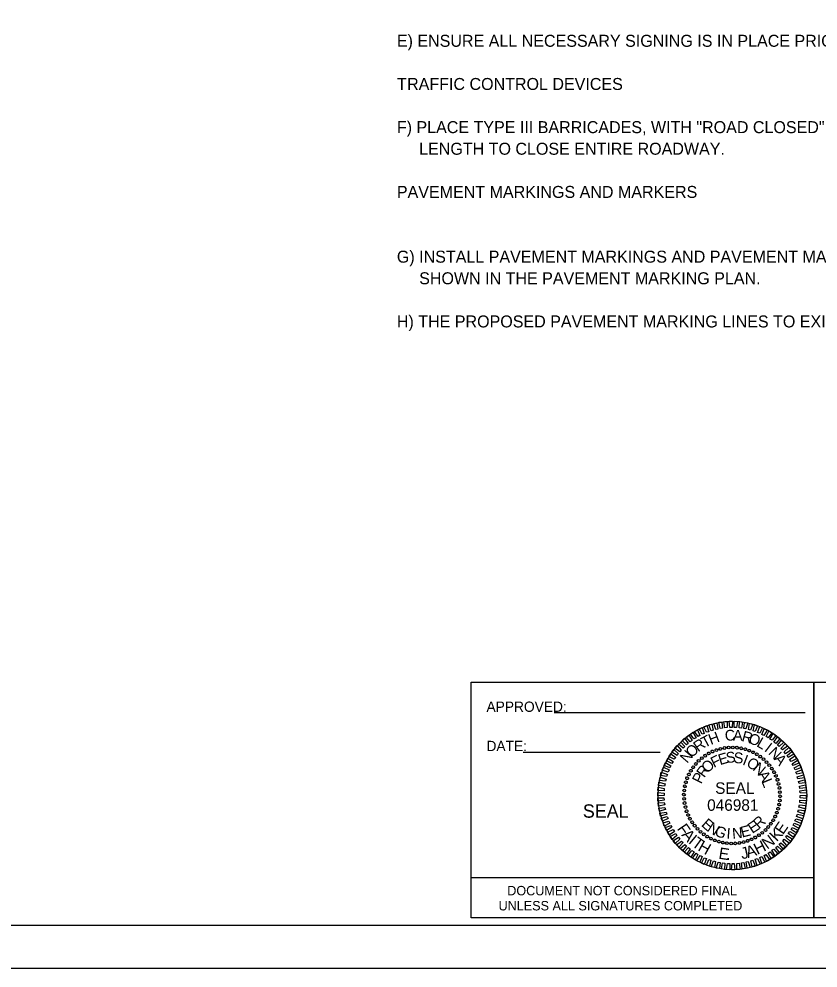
# Model space of a CAD drawing. Extents: x -38542 to 45858, y -25814 to 29186.
# Drawn here: x 1012 to 1478, y -628 to -74 of the extents above; entities that cross this region are included whole.
import ezdxf

# ---------------------------------------------------------------- set-up
doc = ezdxf.new("R2010")
doc.units = 0
for name, color, linetype in [('DEV PORTABLE SIGN CELL', 7, 'Continuous'), ('Exist Road Non-System Type 51 Label', 7, 'Continuous'), ('Sheet Plan CELL', 7, 'Continuous'), ('Sheet Plot Border Outside CELL', 7, 'Continuous'), ('WZ DETAHD CELL', 7, 'Continuous'), ('WZ RC1000 CELL', 7, 'Continuous'), ('WZ RCANR CELL', 7, 'Continuous')]:
    doc.layers.add(name, color=color, linetype=linetype)

msp = doc.modelspace()

# ---------------------------------------------------------------- linework, layer by layer
at = {"layer": 'DEV PORTABLE SIGN CELL'}
for p, q in [((1414.41, -503.12), (1414.41, -503.12)), ((1416.59, -502), (1416.59, -502)), ((1418.83, -501.11), (1418.83, -501.11)), ((1421.17, -500.43), (1421.17, -500.43)), ((1423.63, -499.99), (1423.63, -499.99)), ((1426.03, -499.65), (1426.03, -499.65)), ((1428.49, -499.6), (1428.49, -499.6)), ((1430.95, -499.76), (1430.95, -499.76)), ((1433.35, -500.16), (1433.35, -500.16)), ((1435.7, -500.66), (1435.7, -500.66)), ((1438.05, -501.44), (1438.05, -501.44)), ((1440.28, -502.45), (1440.28, -502.45)), ((1442.46, -503.56), (1442.46, -503.56)), ((1406.81, -509.21), (1406.81, -509.21)), ((1408.49, -507.48), (1408.49, -507.48)), ((1410.33, -505.8), (1410.33, -505.8)), ((1412.29, -504.4), (1412.29, -504.4)), ((1444.48, -504.96), (1444.48, -504.96)), ((1446.43, -506.47), (1446.43, -506.47)), ((1448.16, -508.15), (1448.16, -508.15)), ((1403.9, -513.18), (1403.9, -513.18)), ((1405.3, -511.16), (1405.3, -511.16)), ((1449.84, -509.99), (1449.84, -509.99)), ((1451.24, -511.95), (1451.24, -511.95)), ((1452.52, -514.07), (1452.52, -514.07)), ((1401, -519.94), (1401, -519.94)), ((1401.78, -517.59), (1401.78, -517.59)), ((1402.79, -515.36), (1402.79, -515.36)), ((1453.64, -516.25), (1453.64, -516.25)), ((1454.53, -518.48), (1454.53, -518.48)), ((1400.1, -524.69), (1400.1, -524.69)), ((1400.5, -522.28), (1400.5, -522.28)), ((1455.21, -520.83), (1455.21, -520.83)), ((1455.65, -523.29), (1455.65, -523.29)), ((1455.99, -525.69), (1455.99, -525.69)), ((1399.94, -527.15), (1399.94, -527.15)), ((1399.99, -529.61), (1399.99, -529.61)), ((1427.99, -527.65), (1427.99, -527.65)), ((1455.88, -530.61), (1455.88, -530.61)), ((1456.04, -528.15), (1456.04, -528.15)), ((1400.33, -532.01), (1400.33, -532.01)), ((1400.77, -534.47), (1400.77, -534.47)), ((1401.45, -536.81), (1401.45, -536.81)), ((1454.98, -535.36), (1454.98, -535.36)), ((1455.48, -533.01), (1455.48, -533.01)), ((1402.34, -539.05), (1402.34, -539.05)), ((1403.46, -541.23), (1403.46, -541.23)), ((1452.08, -542.12), (1452.08, -542.12)), ((1453.19, -539.94), (1453.19, -539.94)), ((1454.2, -537.71), (1454.2, -537.71)), ((1404.74, -543.35), (1404.74, -543.35)), ((1406.14, -545.31), (1406.14, -545.31)), ((1407.82, -547.15), (1407.82, -547.15)), ((1447.49, -547.82), (1447.49, -547.82)), ((1449.17, -546.09), (1449.17, -546.09)), ((1450.68, -544.14), (1450.68, -544.14)), ((1409.55, -548.83), (1409.55, -548.83)), ((1411.5, -550.34), (1411.5, -550.34)), ((1413.52, -551.74), (1413.52, -551.74)), ((1415.7, -552.85), (1415.7, -552.85)), ((1417.93, -553.86), (1417.93, -553.86)), ((1439.39, -553.3), (1439.39, -553.3)), ((1441.57, -552.18), (1441.57, -552.18)), ((1443.69, -550.9), (1443.69, -550.9)), ((1445.65, -549.5), (1445.65, -549.5)), ((1420.28, -554.64), (1420.28, -554.64)), ((1422.63, -555.14), (1422.63, -555.14)), ((1425.03, -555.54), (1425.03, -555.54)), ((1427.49, -555.7), (1427.49, -555.7)), ((1429.95, -555.65), (1429.95, -555.65)), ((1432.35, -555.31), (1432.35, -555.31)), ((1434.81, -554.87), (1434.81, -554.87)), ((1437.15, -554.19), (1437.15, -554.19))]:
    msp.add_line(p, q, dxfattribs=at)
for points in [[(1413.07, -490.77), (1411.62, -487.53), (1413.29, -486.85), (1414.47, -490.43)], [(1415.81, -489.87), (1414.52, -486.52), (1416.25, -486.02), (1416.98, -489.48)], [(1418.49, -489.15), (1417.32, -485.63), (1419.22, -485.23), (1419.66, -488.87)], [(1421.17, -488.53), (1420.28, -484.95), (1422.12, -484.79), (1422.51, -488.36)], [(1423.85, -488.2), (1423.24, -484.62), (1425.14, -484.4), (1425.2, -488.03)], [(1426.65, -487.92), (1426.37, -484.28), (1428.21, -484.34), (1427.99, -487.97)], [(1429.33, -487.97), (1429.33, -484.34), (1431.18, -484.4), (1430.67, -488.03)], [(1432.13, -488.14), (1432.35, -484.51), (1434.19, -484.84), (1433.47, -488.36)], [(1434.81, -488.59), (1435.31, -485.01), (1437.15, -485.29), (1436.15, -488.75)], [(1437.66, -489.2), (1438.22, -485.57), (1440.12, -486.02), (1438.83, -489.48)], [(1440.34, -489.93), (1441.18, -486.46), (1442.91, -487.02), (1441.51, -490.32)], [(1442.85, -490.93), (1444.14, -487.41), (1445.71, -488.08), (1444.14, -491.33)], [(1403.62, -496.36), (1401.22, -493.67), (1402.73, -492.5), (1404.69, -495.63)], [(1405.75, -494.68), (1403.68, -491.83), (1405.13, -490.77), (1406.98, -494.01)], [(1408.21, -493.28), (1406.14, -490.26), (1407.87, -489.37), (1409.27, -492.61)], [(1410.61, -491.94), (1408.82, -488.81), (1410.55, -488.03), (1411.84, -491.44)], [(1445.37, -492), (1446.77, -488.7), (1448.5, -489.48), (1446.6, -492.61)], [(1447.94, -493.28), (1449.45, -490.1), (1451.13, -491.05), (1449, -493.95)], [(1450.12, -494.79), (1452.08, -491.55), (1453.53, -492.72), (1451.35, -495.46)], [(1399.55, -500.04), (1396.7, -497.75), (1398.09, -496.47), (1400.44, -499.15)], [(1401.39, -498.09), (1398.93, -495.63), (1400.27, -494.29), (1402.45, -497.31)], [(1452.41, -496.47), (1454.48, -493.39), (1455.93, -494.62), (1453.47, -497.25)], [(1454.53, -498.2), (1456.83, -495.29), (1458.17, -496.63), (1455.6, -499.04)], [(1456.55, -500.16), (1458.95, -497.53), (1460.29, -498.87), (1457.38, -501.05)], [(1394.24, -506.53), (1391.11, -504.85), (1392.22, -503.28), (1395.13, -505.52)], [(1395.91, -504.29), (1392.9, -502.39), (1393.96, -500.77), (1396.64, -503.23)], [(1397.59, -502.17), (1394.68, -499.99), (1395.91, -498.53), (1398.37, -501.16)], [(1458.5, -502.17), (1461.07, -499.65), (1462.25, -501.16), (1459.28, -503.28)], [(1460.18, -504.35), (1462.92, -502), (1463.98, -503.62), (1460.85, -505.41)], [(1391.78, -511.5), (1388.31, -510.21), (1389.15, -508.48), (1392.34, -510.27)], [(1392.9, -508.93), (1389.71, -507.53), (1390.55, -505.8), (1393.57, -507.87)], [(1461.63, -506.64), (1464.59, -504.51), (1465.66, -506.19), (1462.41, -507.76)], [(1463.08, -509.1), (1466.21, -507.14), (1466.94, -508.87), (1463.76, -510.16)], [(1389.82, -516.64), (1386.36, -515.91), (1386.75, -514.07), (1390.27, -515.47)], [(1390.66, -513.96), (1387.19, -512.95), (1387.92, -511.22), (1391.27, -512.78)], [(1464.2, -511.5), (1467.5, -509.82), (1468.23, -511.61), (1464.76, -512.73)], [(1465.21, -514.13), (1468.62, -512.67), (1469.23, -514.41), (1465.77, -515.3)], [(1388.65, -522.17), (1385.07, -521.84), (1385.29, -519.94), (1388.93, -520.83)], [(1389.09, -519.32), (1385.63, -518.88), (1386.02, -516.98), (1389.54, -518.15)], [(1466.1, -516.81), (1469.68, -515.52), (1470.01, -517.37), (1466.49, -517.98)], [(1466.77, -519.49), (1470.29, -518.43), (1470.63, -520.33), (1467.11, -520.66)], [(1388.31, -527.65), (1384.68, -527.82), (1384.68, -525.92), (1388.31, -526.31)], [(1388.37, -524.86), (1384.74, -524.74), (1384.85, -522.9), (1388.48, -523.51)], [(1467.28, -522.17), (1470.91, -521.39), (1471.08, -523.29), (1467.5, -523.51)], [(1467.61, -524.86), (1471.24, -524.41), (1471.36, -526.31), (1467.72, -526.2)], [(1388.37, -530.44), (1384.74, -530.89), (1384.62, -528.99), (1388.26, -529.1)], [(1467.61, -530.44), (1471.24, -530.56), (1471.13, -532.4), (1467.5, -531.79)], [(1467.67, -527.65), (1471.3, -527.48), (1471.3, -529.38), (1467.67, -528.99)], [(1388.7, -533.13), (1385.07, -533.91), (1384.9, -532.01), (1388.48, -531.79)], [(1389.21, -535.81), (1385.69, -536.87), (1385.35, -534.97), (1388.87, -534.64)], [(1466.88, -535.98), (1470.35, -536.42), (1469.96, -538.32), (1466.44, -537.15)], [(1467.33, -533.13), (1470.91, -533.46), (1470.68, -535.36), (1467.05, -534.47)], [(1389.88, -538.49), (1386.3, -539.78), (1385.97, -537.93), (1389.49, -537.32)], [(1390.77, -541.17), (1387.36, -542.63), (1386.75, -540.89), (1390.21, -540)], [(1391.78, -543.8), (1388.48, -545.48), (1387.75, -543.69), (1391.22, -542.57)], [(1465.32, -541.34), (1468.78, -542.35), (1468.06, -544.08), (1464.71, -542.51)], [(1466.16, -538.66), (1469.62, -539.39), (1469.23, -541.23), (1465.71, -539.83)], [(1392.9, -546.2), (1389.77, -548.16), (1389.04, -546.43), (1392.22, -545.14)], [(1394.35, -548.66), (1391.39, -550.79), (1390.32, -549.11), (1393.57, -547.54)], [(1463.08, -546.37), (1466.27, -547.77), (1465.43, -549.5), (1462.41, -547.43)], [(1464.2, -543.8), (1467.67, -545.09), (1466.83, -546.82), (1463.64, -545.03)], [(1395.8, -550.95), (1393.06, -553.3), (1392, -551.68), (1395.13, -549.89)], [(1397.48, -553.13), (1394.91, -555.65), (1393.73, -554.14), (1396.7, -552.02)], [(1458.39, -553.13), (1461.3, -555.31), (1460.07, -556.77), (1457.61, -554.14)], [(1460.07, -551.01), (1463.08, -552.91), (1462.02, -554.53), (1459.34, -552.07)], [(1461.74, -548.77), (1464.87, -550.45), (1463.76, -552.02), (1460.85, -549.78)], [(1399.43, -555.14), (1397.03, -557.77), (1395.69, -556.43), (1398.6, -554.25)], [(1401.45, -557.1), (1399.15, -560.01), (1397.81, -558.67), (1400.38, -556.26)], [(1403.57, -558.83), (1401.5, -561.91), (1400.05, -560.68), (1402.51, -558.05)], [(1452.36, -558.94), (1454.76, -561.63), (1453.25, -562.8), (1451.29, -559.67)], [(1454.59, -557.21), (1457.05, -559.67), (1455.71, -561.01), (1453.53, -557.99)], [(1456.43, -555.26), (1459.28, -557.55), (1457.89, -558.83), (1455.54, -556.15)], [(1405.86, -560.51), (1403.9, -563.75), (1402.45, -562.58), (1404.63, -559.84)], [(1408.04, -562.02), (1406.53, -565.2), (1404.85, -564.25), (1406.98, -561.35)], [(1410.61, -563.3), (1409.21, -566.6), (1407.48, -565.82), (1409.38, -562.69)], [(1413.12, -564.37), (1411.84, -567.89), (1410.27, -567.22), (1411.84, -563.97)], [(1415.64, -565.37), (1414.8, -568.84), (1413.07, -568.28), (1414.47, -564.98)], [(1442.91, -564.53), (1444.36, -567.77), (1442.69, -568.44), (1441.51, -564.87)], [(1445.37, -563.36), (1447.16, -566.49), (1445.43, -567.27), (1444.14, -563.86)], [(1447.77, -562.02), (1449.84, -565.04), (1448.11, -565.93), (1446.71, -562.69)], [(1450.23, -560.62), (1452.3, -563.47), (1450.85, -564.53), (1449, -561.29)], [(1418.32, -566.1), (1417.76, -569.73), (1415.86, -569.28), (1417.15, -565.82)], [(1421.17, -566.71), (1420.67, -570.29), (1418.83, -570.01), (1419.83, -566.54)], [(1423.85, -567.16), (1423.63, -570.79), (1421.79, -570.46), (1422.51, -566.94)], [(1426.65, -567.33), (1426.65, -570.96), (1424.8, -570.9), (1425.31, -567.27)], [(1429.33, -567.38), (1429.61, -571.02), (1427.77, -570.96), (1427.99, -567.33)], [(1432.13, -567.1), (1432.74, -570.68), (1430.84, -570.9), (1430.78, -567.27)], [(1434.81, -566.77), (1435.7, -570.34), (1433.86, -570.51), (1433.47, -566.94)], [(1437.49, -566.15), (1438.66, -569.67), (1436.76, -570.07), (1436.32, -566.43)], [(1440.17, -565.43), (1441.46, -568.78), (1439.73, -569.28), (1439, -565.82)]]:
    msp.add_lwpolyline(points, close=True, dxfattribs=at)
for centre, major_axis in [((1412.32, -504.41), (-0.45, 0.667)), ((1414.4, -503.13), (-0.39, 0.704)), ((1416.59, -502.04), (-0.327, 0.735)), ((1418.86, -501.15), (-0.262, 0.761)), ((1421.21, -500.45), (-0.195, 0.781)), ((1423.6, -499.96), (-0.126, 0.795)), ((1426.03, -499.69), (-0.056, 0.803)), ((1428.48, -499.62), (0.014, 0.805)), ((1430.92, -499.77), (0.084, 0.8)), ((1433.34, -500.13), (0.154, 0.79)), ((1435.72, -500.7), (0.222, 0.774)), ((1438.04, -501.48), (0.288, 0.751)), ((1440.28, -502.46), (0.353, 0.723)), ((1442.43, -503.62), (0.414, 0.69)), ((1406.83, -509.26), (-0.607, 0.528)), ((1408.52, -507.49), (-0.559, 0.579)), ((1410.35, -505.87), (-0.506, 0.625)), ((1444.47, -504.97), (0.473, 0.651)), ((1446.38, -506.49), (0.528, 0.607)), ((1448.15, -508.18), (0.579, 0.559)), ((1449.77, -510.01), (0.625, 0.506)), ((1402.8, -515.36), (-0.723, 0.353)), ((1403.96, -513.21), (-0.69, 0.414)), ((1405.31, -511.17), (-0.651, 0.473)), ((1451.23, -511.97), (0.667, 0.45)), ((1452.51, -514.06), (0.704, 0.39)), ((1401.04, -519.92), (-0.774, 0.222)), ((1401.82, -517.6), (-0.751, 0.288)), ((1453.6, -516.25), (0.735, 0.327)), ((1454.49, -518.52), (0.761, 0.262)), ((1455.19, -520.87), (0.781, 0.195)), ((1400.11, -524.72), (-0.8, 0.084)), ((1400.47, -522.3), (-0.79, 0.154)), ((1455.68, -523.26), (0.795, 0.126)), ((1455.95, -525.69), (0.803, 0.056)), ((1399.96, -527.16), (-0.805, 0.014)), ((1400.03, -529.61), (-0.803, -0.056)), ((1400.3, -532.03), (-0.795, -0.126)), ((1455.87, -530.58), (0.8, -0.084)), ((1456.02, -528.14), (0.805, -0.014)), ((1400.79, -534.43), (-0.781, -0.195)), ((1401.49, -536.78), (-0.761, -0.262)), ((1454.16, -537.7), (0.751, -0.288)), ((1454.94, -535.38), (0.774, -0.222)), ((1455.51, -533), (0.79, -0.154)), ((1402.38, -539.05), (-0.735, -0.327)), ((1403.47, -541.24), (-0.704, -0.39)), ((1404.75, -543.32), (-0.667, -0.45)), ((1452.02, -542.09), (0.69, -0.414)), ((1453.18, -539.94), (0.723, -0.353)), ((1406.21, -545.29), (-0.625, -0.506)), ((1407.83, -547.12), (-0.579, -0.559)), ((1409.6, -548.81), (-0.528, -0.607)), ((1447.46, -547.81), (0.559, -0.579)), ((1449.15, -546.04), (0.607, -0.528)), ((1450.67, -544.13), (0.651, -0.473)), ((1411.51, -550.33), (-0.473, -0.651)), ((1413.55, -551.68), (-0.414, -0.69)), ((1415.7, -552.84), (-0.353, -0.723)), ((1417.94, -553.82), (-0.288, -0.751)), ((1420.26, -554.6), (-0.222, -0.774)), ((1437.12, -554.15), (0.262, -0.761)), ((1439.39, -553.26), (0.327, -0.735)), ((1441.58, -552.17), (0.39, -0.704)), ((1443.66, -550.89), (0.45, -0.667)), ((1445.63, -549.43), (0.506, -0.625)), ((1422.64, -555.17), (-0.154, -0.79)), ((1425.06, -555.53), (-0.084, -0.8)), ((1427.5, -555.68), (-0.014, -0.805)), ((1429.95, -555.61), (0.056, -0.803)), ((1432.37, -555.34), (0.126, -0.795)), ((1434.77, -554.85), (0.195, -0.781))]:
    msp.add_ellipse(centre, major_axis=major_axis, ratio=0.999708, dxfattribs=at)
at = {"layer": 'Exist Road Non-System Type 51 Label'}
msp.add_lwpolyline([(1830.96, 446.64), (330.96, 446.64), (330.96, -603.36), (1830.96, -603.36)], close=True, dxfattribs=at)
at = {"layer": 'Sheet Plot Border Outside CELL'}
msp.add_lwpolyline([(167.97, -628.36), (1855.96, -628.36), (1855.96, 471.64), (167.97, 471.64)], close=True, dxfattribs=at)
at = {"layer": 'WZ DETAHD CELL'}
for p, q in [((1275.78, -599.09), (1275.78, -575.59)), ((1275.78, -575.59), (1475.81, -575.59)), ((1475.81, -575.6), (1475.81, -599.1)), ((1475.81, -599.09), (1275.78, -599.09))]:
    msp.add_line(p, q, dxfattribs=at)
at = {"layer": 'WZ RC1000 CELL'}
for p, q in [((1324.32, -479.27), (1470.66, -479.27)), ((1475.81, -485.09), (1475.81, -599.09)), ((1306.21, -502.35), (1386, -502.35))]:
    msp.add_line(p, q, dxfattribs=at)
for points in [[(1275.78, -461.59), (1475.81, -461.59), (1475.81, -599.09), (1275.78, -599.09)], [(1475.81, -461.59), (1589.81, -461.59), (1589.81, -599.09), (1475.81, -599.09)]]:
    msp.add_lwpolyline(points, close=True, dxfattribs=at)
msp.add_circle((1428.21, -527.68), 43.34, dxfattribs=at)

# ---------------------------------------------------------------- texts
at = {"layer": 'DEV PORTABLE SIGN CELL'}
for s, height, rotation, p in [('T', 6.3, 27.8198, (1412.01, -500.04)), ('H', 6.3, 20.6195, (1415.64, -498.2)), ('C', 6.3, 6.2199, (1424.13, -495.96)), ('A', 6.3, 359.0203, (1428.55, -495.63)), ('R', 6.3, 344.6211, (1433.24, -495.85)), ('O', 6.3, 337.4212, (1436.99, -496.69)), ('O', 6.3, 42.2217, (1404.35, -505.97)), ('R', 6.3, 35.0205, (1408.21, -502.5)), ('L', 6.3, 330.2209, (1441.9, -498.76)), ('I', 6.3, 323.0201, (1446.43, -501.44)), ('N', 6.3, 49.4235, (1401.78, -509.21)), ('F', 6.3, 25.967, (1417.43, -511.67)), ('E', 6.3, 16.6111, (1421, -509.99)), ('S', 6.3, 7.2556, (1424.86, -508.82)), ('S', 6.3, 357.9004, (1428.88, -508.76)), ('I', 6.3, 339.1896, (1433.69, -509.54)), ('N', 6.3, 315.8189, (1448.83, -503.17)), ('O', 6.3, 44.6812, (1413.74, -514.96)), ('O', 6.3, 329.8335, (1435.93, -510.33)), ('N', 6.3, 320.4766, (1439.67, -512.56)), ('A', 6.3, 308.6172, (1452.13, -506.47)), ('P', 6.3, 63.3989, (1410, -521.28)), ('R', 6.3, 54.0397, (1411.78, -517.7)), ('A', 6.3, 301.7603, (1442.85, -515.47)), ('SEAL', 6.704, 360, (1418.16, -526.7)), ('L', 6.3, 292.4009, (1445.03, -519.32)), ('E', 6.3, 318.2769, (1409.66, -545.14)), ('E', 6.3, 33.1241, (1439.78, -550.12)), ('R', 6.3, 42.4814, (1443.75, -547.49)), ('E', 6.7, 55.493, (1457.72, -550.89)), ('F', 6.7, 304.4142, (1395.61, -547.03)), ('A', 6.7, 311.4309, (1398.22, -550.84)), ('N', 6.3, 327.634, (1413.01, -548.16)), ('G', 6.3, 336.9902, (1417.26, -550.67)), ('I', 6.3, 355.7012, (1424.58, -552.8)), ('N', 6.3, 5.0564, (1428.33, -552.97)), ('E', 6.3, 14.4118, (1433.86, -552.29)), ('K', 6.7, 47.2091, (1454.06, -554.93)), ('I', 6.7, 320.2712, (1402.14, -555.14)), ('T', 6.7, 324.0731, (1404.02, -556.8)), ('H', 6.7, 26.4993, (1442.73, -562.39)), ('N', 6.7, 36.4833, (1448.53, -559.31)), ('H', 6.7, 330.8733, (1407.64, -559.43)), ('E', 6.7, 351.0577, (1419.86, -564.5)), ('J', 6.7, 12.4012, (1433.83, -564.93)), ('A', 6.7, 17.659, (1437.22, -564.24)), ('.', 6.7, 358.167, (1424.48, -565.22))]:
    msp.add_text(s, height=height, rotation=rotation, dxfattribs=at).set_placement(p)
msp.add_text('046981', height=6.704, dxfattribs=at).set_placement((1413.49, -536.6))
at = {"layer": 'Sheet Plan CELL'}
for s, p in [('E) ENSURE ALL NECESSARY SIGNING IS IN PLACE PRIOR TO ALTERING ANY TRAFFIC PATTERN.', (1232.45, -90.69)), ('T', (1232.45, -115.89)), ('RAFFIC CONTROL DEVICES', (1238.42, -115.89)), ('F) PLACE TYPE III BARRICADES, WITH "ROAD CLOSED" SIGN R11-2 ATTACHED, OF SUFFICIENT', (1232.45, -141.09)), ('     LENGTH TO CLOSE ENTIRE ROADWAY.', (1232.45, -153.69)), ('PAVEMENT MARKINGS AND MARKERS', (1232.45, -178.89)), ('G) INSTALL PAVEMENT MARKINGS AND PAVEMENT MARKERS ON THE FINAL SURFACE, AS ', (1232.45, -216.69)), ('     SHOWN IN THE PAVEMENT MARKING PLAN.', (1232.45, -229.29)), ('H) THE PROPOSED PAVEMENT MARKING LINES TO EXISTING PAVEMENT MARKING LINES.', (1232.45, -254.49))]:
    msp.add_text(s, height=7, rotation=0, dxfattribs=at).set_placement(p)
at = {"layer": 'WZ DETAHD CELL'}
for s, p in [('DOCUMENT NOT CONSIDERED FINAL', (1296.85, -585.94)), ('UNLESS ALL SIGNATURES COMPLETED', (1291.78, -594.74))]:
    msp.add_text(s, height=5.5, dxfattribs=at).set_placement(p)
at = {"layer": 'WZ RC1000 CELL'}
for s, p in [('APPROVED:  ', (1284.74, -478.84)), ('DATE:  ', (1284.74, -501.75))]:
    msp.add_text(s, height=6, dxfattribs=at).set_placement(p)
at = {"layer": 'WZ RCANR CELL'}
msp.add_text('SEAL', height=7.812, dxfattribs=at).set_placement((1340.95, -540.64))

doc.saveas('drawing.dxf')
